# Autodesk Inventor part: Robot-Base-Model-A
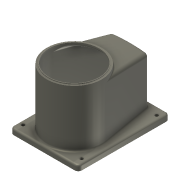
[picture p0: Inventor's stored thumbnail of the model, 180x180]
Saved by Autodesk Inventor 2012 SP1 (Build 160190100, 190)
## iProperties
Shininess: 21.0
Length Units: 11269
Angle Units: 11279
Time Units: 11290
Mass Units: 11283
Length Display Precision: 3
Angle Display Precision: 2
Created: 2001-08
Part Number: Robot-Base-Model-A
Document SubType Name: ﾓﾃﾞﾘﾝｸﾞ
Designer: Administrator
Density: 1 g/cm^3
Material: Default
Density: 0.0
Volumn: 0.0
Area: 0.0
PropertySet Name: Model Information
Control State: 0
Master: False
Checked Out: False
Author: Administrator
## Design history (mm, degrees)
node "Center-Work Plane"
fillet "Chamfer1" dims "d14" = 10
fillet "Chamfer2" dims "d15" = 5
fillet "Chamfer3" dims "d16" = 10
fillet "Chamfer4" dims "d30" = 5
shell "Shell1" dims "d34" = 2
body "Solid1"
sketch "Sketch1"
  geometry: L1 (-93, 168)-(93, 168); L2 (93, 168)-(93, -82); L3 (93, -82)-(-93, -82); L4 (-93, -82)-(-93, 168); L5 (-93, 0)-(93, 0); L6 (0, 168)-(0, -82); 2 further points
  constraints: 12 end point, 3 midpoint, 3 point on line, 2 parallel, 1 coincident, 1 horizontal, 1 perpendicular, 1 other
  dimensions: "d0" = 250 distance of L3.end L1.start; "d1" = 186 distance of L1.start L1.end; "d2" = 82 distance between parallel lines of L3 L5
extrude "Extrusion1" new body sketch "Sketch1" distance "d3" = 15; taper "d4" = 0 deg
sketch "Sketch2"
  geometry: C1 r 75 at (0, 0)
  constraints: 1 centre point
  dimensions: "d5" = 150 diameter of C1
extrude "Extrusion2" join sketch "Sketch2" distance "d6" = 155; taper "d7" = 0 deg
sketch "Sketch3"
  geometry: L1 (-93, 168)-(93, 168) reference; L2 (-50, 153)-(50, 153); L3 (0, 197.064)-(0, -91.178); L4 (50, 153)-(73.933, 12.603); L5 (-50, 153)-(-73.933, 12.603); L6 (-73.933, 12.603)-(73.933, 12.603); A1 r 75 centre (0, 0) between (73.933, 12.603) and (-73.933, 12.603) reference
  constraints: 10 end point, 2 point on circle, 2 tangent, 1 parallel, 1 perpendicular, 1 point on line
  dimensions: "d8" = 50 distance from line of L2.start L3; "d9" = 50 distance from line of L2.end L3; "d10" = 15 distance between parallel lines of L2 L1
extrude "Extrusion3" join sketch "Sketch3" distance "d11" = 145; taper "d12" = 0 deg
feature "FaceDraft" dims angle "d13" = 10 deg
sketch "Sketch4"
  geometry: L1 (-93, -72)-(-93, 158) reference; L2 (-80, 145)-(80, 145); L3 (-80, 145)-(-80, -173.228); L4 (80, 145)-(80, -173.228); L5 (-80, -60)-(80, -60); L6 (0, 145)-(0, -60); 5 further points
  constraints: 10 end point, 4 coincident, 3 point on line, 2 midpoint, 2 parallel, 2 perpendicular, 1 other
  dimensions: "d19" = 160 distance between parallel lines of L4 L3; "d21" = 205 distance between parallel lines of L5 L2; "d22" = 60 distance from line of L5 point (0, 0)
hole "Hole1" sketch "Sketch4" diameter "d23" = 9; stored, may be unused: countersink angle "d27" = 82 deg, drill point angle "d29" = 118 deg; dims "d24" = 6, "d25" = 4, "d26" = 2, "d28" = 8
sketch "Sketch5"
  geometry: C1 r 75 at (0, 0) reference; C2 r 70 at (0, 0)
  constraints: 1 centre point
  dimensions: "d31" = 5 radial gap between concentric circles of C1 C2
extrude "Extrusion4" join sketch "Sketch5" distance "d32" = 2; taper "d33" = 0 deg
